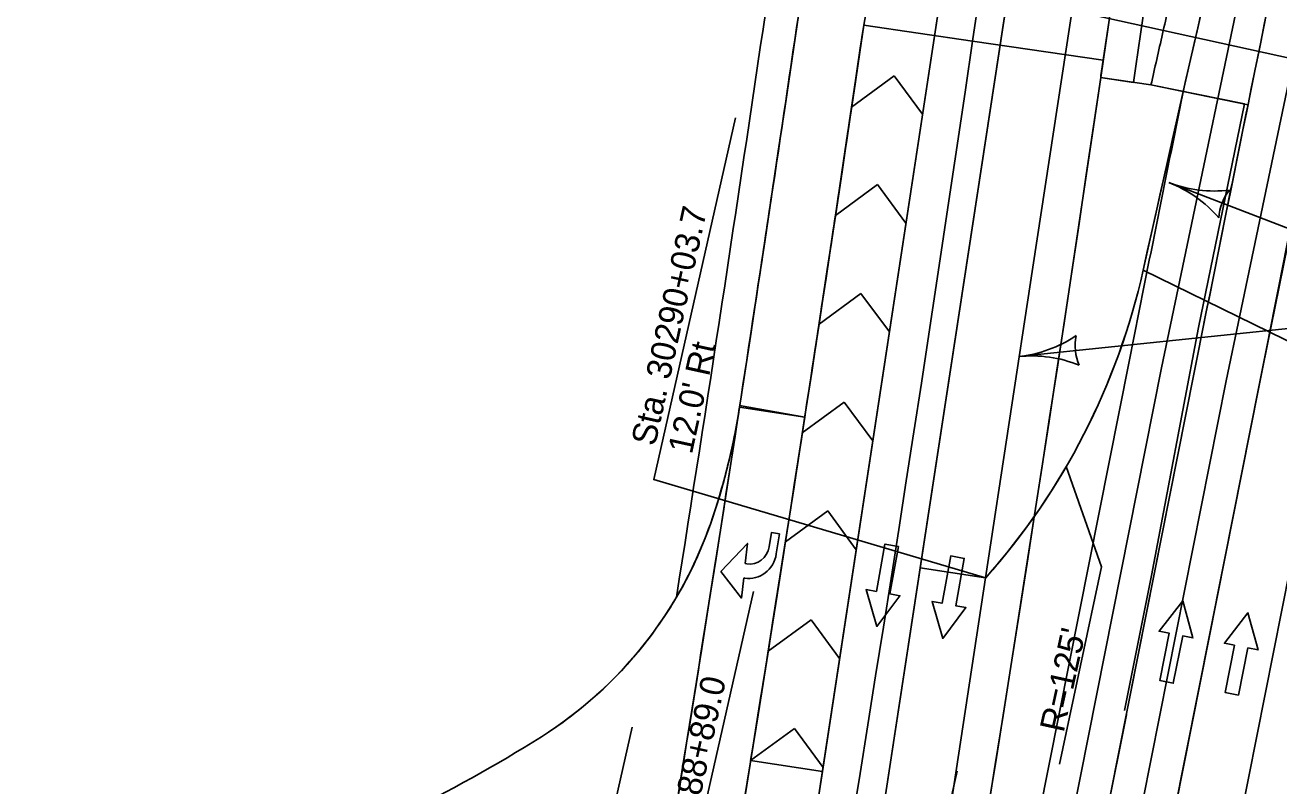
# Model space of a CAD drawing. Extents: x 14104283 to 14120882, y 8635219 to 8671666.
# Drawn here: x 14107792.5 to 14108020.4, y 8639938.3 to 8640076.6 of the extents above; entities that cross this region are included whole.
import ezdxf

# ---------------------------------------------------------------- set-up
doc = ezdxf.new("R2010")
doc.units = 0
for name, color, linetype in [('Cell', 7, 'Continuous'), ('dsnNonPlotable', 7, 'Continuous'), ('dsnPaintExistingBrokenLaneLineWhite', 7, 'Continuous'), ('dsnPaintExistingChannelizingLaneWhite', 7, 'Continuous'), ('dsnPaintExistingEdgeLineRightWhite', 7, 'Continuous'), ('dsnPaintPlaceBrokenLaneLineWhite', 7, 'Continuous'), ('dsnPaintPlaceBrokenLaneWhite', 7, 'Continuous'), ('dsnPaintPlaceEdgeLineLeftYellow', 7, 'Continuous'), ('dsnPaintPlaceEdgeLineRightWhite', 7, 'Continuous'), ('dsnPaintRemoveEdgeLineWhite', 7, 'Continuous'), ('dsnPaintRemoveEdgeLineYellow', 7, 'Continuous'), ('dsnShadingPaved', 7, 'Continuous'), ('dsnStdLabel', 7, 'Continuous'), ('dsnStgShadingPrevPav', 7, 'Continuous'), ('Text', 7, 'Continuous')]:
    doc.layers.add(name, color=color, linetype=linetype)

msp = doc.modelspace()

# ---------------------------------------------------------------- linework, layer by layer
at = {"layer": 'Cell'}
for p, q in [((14107923.72, 8639978.66), (14107923.41, 8639978.71)), ((14107923.13, 8639976.09), (14107923.31, 8639976.06))]:
    msp.add_line(p, q, dxfattribs=at)
for points in [[(14107929.06, 8639980.47), (14107929.64, 8639984.1), (14107928.16, 8639984.34), (14107927.75, 8639981.74)], [(14107929.06, 8639980.47), (14107929.64, 8639984.1), (14107928.16, 8639984.34), (14107927.75, 8639981.74)], [(14107923.41, 8639978.71), (14107923.81, 8639982.37), (14107918.97, 8639977.29)], [(14107923.41, 8639978.71), (14107923.81, 8639982.37), (14107918.97, 8639977.29)], [(14107947.24, 8639973.65), (14107945.39, 8639973.99), (14107947.35, 8639967.28), (14107951.54, 8639972.87), (14107949.7, 8639973.2), (14107951.26, 8639981.81), (14107948.8, 8639982.26), (14107947.24, 8639973.65)], [(14107959.2, 8639971.49), (14107957.36, 8639971.82), (14107959.31, 8639965.11), (14107963.51, 8639970.7), (14107961.66, 8639971.04), (14107963.23, 8639979.65), (14107960.77, 8639980.1), (14107959.2, 8639971.49)], [(14107918.97, 8639977.29), (14107922.73, 8639972.43), (14107923.13, 8639976.09)], [(14107918.97, 8639977.29), (14107922.73, 8639972.43), (14107923.13, 8639976.09)], [(14107923.72, 8639978.66), (14107923.41, 8639978.71)], [(14107923.13, 8639976.09), (14107923.31, 8639976.06)], [(14108002.93, 8639965.55), (14108004.77, 8639965.19), (14108002.93, 8639971.93), (14107998.64, 8639966.41), (14108000.48, 8639966.04), (14107998.76, 8639957.46), (14108001.21, 8639956.97), (14108002.93, 8639965.55)], [(14108014.78, 8639963.38), (14108016.62, 8639963.02), (14108014.78, 8639969.76), (14108010.49, 8639964.24), (14108012.33, 8639963.87), (14108010.61, 8639955.29), (14108013.06, 8639954.8), (14108014.78, 8639963.38)]]:
    msp.add_lwpolyline(points, dxfattribs=at)
for points in [[(14107948.8, 8639982.26), (14107951.26, 8639981.81), (14107949.7, 8639973.2), (14107951.54, 8639972.87), (14107947.35, 8639967.28), (14107945.39, 8639973.99), (14107947.24, 8639973.65)], [(14107960.77, 8639980.1), (14107963.23, 8639979.65), (14107961.66, 8639971.04), (14107963.51, 8639970.7), (14107959.31, 8639965.11), (14107957.36, 8639971.82), (14107959.2, 8639971.49)], [(14108001.21, 8639956.97), (14107998.76, 8639957.46), (14108000.48, 8639966.04), (14107998.64, 8639966.41), (14108002.93, 8639971.93), (14108004.77, 8639965.19), (14108002.93, 8639965.55)], [(14108013.06, 8639954.8), (14108010.61, 8639955.29), (14108012.33, 8639963.87), (14108010.49, 8639964.24), (14108014.78, 8639969.76), (14108016.62, 8639963.02), (14108014.78, 8639963.38)]]:
    msp.add_lwpolyline(points, close=True, dxfattribs=at)
for centre, major_axis in [((14107924.3, 8639982.29), (0.58, 3.63)), ((14107924.3, 8639982.29), (0.58, 3.63)), ((14107924.14, 8639981.25), (0.83, 5.19)), ((14107924.14, 8639981.25), (0.83, 5.19))]:
    msp.add_ellipse(centre, major_axis=major_axis, ratio=0.9474, start_param=3.141593, end_param=4.712389, dxfattribs=at)
at = {"layer": 'dsnNonPlotable'}
msp.add_lwpolyline([(14107218.44, 8638642.33), (14107554.83, 8640173.31), (14108541.3, 8639956.56), (14108204.91, 8638425.58)], close=True, dxfattribs=at)
at = {"layer": 'dsnPaintExistingBrokenLaneLineWhite'}
msp.add_line((14107897.23, 8639597.8), (14108002.8, 8640289.8), dxfattribs=at)
at = {"layer": 'dsnPaintExistingChannelizingLaneWhite'}
for p, q in [((14107990.94, 8640291.61), (14107937.44, 8639940.91)), ((14107950.5, 8640067.36), (14107942.75, 8640061.66)), ((14107955.65, 8640060.36), (14107950.5, 8640067.36)), ((14107947.47, 8640047.59), (14107939.81, 8640041.95)), ((14107952.63, 8640040.58), (14107947.47, 8640047.59)), ((14107944.45, 8640027.82), (14107936.82, 8640022.21)), ((14107949.61, 8640020.8), (14107944.45, 8640027.82)), ((14107941.42, 8640008.05), (14107933.79, 8640002.44)), ((14107946.6, 8640001.01), (14107941.42, 8640008.05)), ((14107938.4, 8639988.28), (14107930.71, 8639982.63)), ((14107943.58, 8639981.23), (14107938.4, 8639988.28)), ((14107935.37, 8639968.51), (14107927.58, 8639962.78)), ((14107940.57, 8639961.44), (14107935.37, 8639968.51)), ((14107932.34, 8639948.74), (14107924.4, 8639942.9)), ((14107937.55, 8639941.65), (14107932.34, 8639948.74)), ((14107937.44, 8639940.91), (14107924.4, 8639942.9))]:
    msp.add_line(p, q, dxfattribs=at)
for centre, radius, start, end in [((14098631.47, 8641759.51), 9464.31, 349.754833, 350.304675), ((14098576.76, 8641447.78), 9468, 350.854404, 351.672846)]:
    msp.add_arc(centre, radius, start, end, dxfattribs=at)
at = {"layer": 'dsnPaintExistingEdgeLineRightWhite'}
for centre, radius, start, end in [((14098576.76, 8641447.78), 9456, 351.234366, 351.672846), ((14107805.1, 8640025.1), 118.64, 340.7006, 351.1759), ((14107846.26, 8640010.61), 75, 302.3186, 340.7615), ((14107752.7, 8640158.5), 250, 288.9195, 302.3186)]:
    msp.add_arc(centre, radius, start, end, dxfattribs=at)
at = {"layer": 'dsnPaintPlaceBrokenLaneLineWhite'}
msp.add_lwpolyline([(14107985.48, 8639853.32), (14108001.11, 8639932.06), (14108016.73, 8640010.8), (14108028.7, 8640069.55), (14108040.67, 8640128.3), (14108053.24, 8640186.93), (14108065.81, 8640245.56), (14108082.44, 8640321.29), (14108099.08, 8640397.01)], dxfattribs=at)
at = {"layer": 'dsnPaintPlaceBrokenLaneWhite'}
msp.add_lwpolyline([(14107843.64, 8639178.31), (14107884.58, 8639364.68), (14107924.33, 8639550.14), (14107962.2, 8639735.99), (14107989.47, 8639873.39), (14108016.73, 8640010.79)], dxfattribs=at)
at = {"layer": 'dsnPaintPlaceEdgeLineLeftYellow'}
for p, q in [((14108014.66, 8640287.99), (14107975.68, 8640032.58)), ((14107975.68, 8640032.58), (14107967.07, 8639976.09))]:
    msp.add_line(p, q, dxfattribs=at)
for centre, radius, start, end in [((14119521.42, 8637460.89), 11808.99, 166.339341, 167.424478), ((14107873.73, 8640059.23), 125, 318.3035, 347.4245)]:
    msp.add_arc(centre, radius, start, end, dxfattribs=at)
at = {"layer": 'dsnPaintPlaceEdgeLineRightWhite'}
msp.add_lwpolyline([(14107997.25, 8639850.98), (14108001.23, 8639871.02), (14108028.5, 8640008.43), (14108052.42, 8640125.85), (14108077.53, 8640243.01), (14108094.16, 8640318.73), (14108110.8, 8640394.44)], dxfattribs=at)
at = {"layer": 'dsnPaintRemoveEdgeLineWhite'}
msp.add_lwpolyline([(14107811.17, 8639057.08), (14107844.94, 8639211.53), (14107878.72, 8639365.97), (14107918.46, 8639551.34), (14107956.3, 8639737.1), (14108010.84, 8640011.94), (14108059.95, 8640246.87), (14108093.19, 8640398.18)], dxfattribs=at)
at = {"layer": 'dsnPaintRemoveEdgeLineYellow'}
msp.add_lwpolyline([(14107799.44, 8639059.65), (14107867, 8639368.55), (14107944.53, 8639739.44), (14107999.07, 8640014.27), (14108048.23, 8640249.45), (14108081.5, 8640400.87)], dxfattribs=at)
at = {"layer": 'dsnShadingPaved'}
for p, q in [((14107885.37, 8639599.61), (14107990.94, 8640291.61)), ((14108002.8, 8640289.8), (14107897.23, 8639597.8)), ((14107955.22, 8639977.91), (14108002.8, 8640289.8)), ((14108014.66, 8640287.99), (14107975.68, 8640032.58)), ((14107995.73, 8640032.02), (14108003.03, 8640064.5)), ((14108003.03, 8640064.5), (14108014.79, 8640062.11)), ((14108014.79, 8640062.11), (14108003.03, 8640064.5)), ((14107975.68, 8640032.58), (14107967.07, 8639976.1)), ((14108004.96, 8640013.11), (14107973.63, 8639855.23)), ((14107922.35, 8640007.41), (14107934.24, 8640005.32)), ((14107922.38, 8640007.15), (14107934.24, 8640005.32)), ((14107897.23, 8639597.8), (14107955.22, 8639977.91)), ((14107967.07, 8639976.1), (14107955.22, 8639977.91)), ((14107955.22, 8639977.91), (14107967.07, 8639976.1)), ((14107949.24, 8639859.12), (14107967.08, 8639976.1)), ((14107967.08, 8639976.1), (14107949.24, 8639859.12)), ((14107937.44, 8639940.91), (14107908.71, 8639752.63)), ((14107924.4, 8639942.9), (14107937.44, 8639940.91))]:
    msp.add_line(p, q, dxfattribs=at)
for points in [[(14107831.92, 8639180.86), (14107872.85, 8639367.2), (14107912.58, 8639552.57), (14107950.43, 8639738.33), (14108004.96, 8640013.11)], [(14108028.5, 8640008.43), (14107973.96, 8639733.6), (14107936.08, 8639547.66), (14107896.3, 8639362.11), (14107855.36, 8639175.71)]]:
    msp.add_lwpolyline(points, dxfattribs=at)
for centre, radius, start, end in [((14119521.42, 8637460.89), 11808.99, 166.339341, 167.262962), ((14119581.23, 8637715.91), 11802, 167.610212, 168.776036), ((14119581.23, 8637715.91), 11802, 167.610212, 168.533379), ((14098631.47, 8641759.51), 9464.31, 349.754833, 350.304675), ((14098576.76, 8641447.78), 9456, 351.23682, 351.672846), ((14098576.76, 8641447.78), 9468, 351.23682, 351.672846), ((14119581.23, 8637715.91), 11802, 168.533379, 168.776036), ((14107873.73, 8640059.23), 125, 318.3138, 347.4245), ((14107803.78, 8640025.43), 120, 340.7615, 351.2368), ((14098576.76, 8641447.78), 9468, 350.854404, 351.23682), ((14107846.26, 8640010.61), 75, 302.3186, 340.7615), ((14107752.7, 8640158.5), 250, 288.9195, 302.3186)]:
    msp.add_arc(centre, radius, start, end, dxfattribs=at)
at = {"layer": 'dsnStdLabel'}
for q in [(14108000.38, 8640047.95), (14107973.08, 8640016.33)]:
    msp.add_line((14108059.33, 8640025.28), q, dxfattribs=at)
for centre, radius, start, end in [((14107992.15, 8640026.53), 22.95, 40.892, 68.9633), ((14108008.62, 8640069.37), 22.95, 248.9631, 277.0344), ((14108018.34, 8640041.04), 8.86, 141.2289, 176.6974), ((14107970.71, 8640039.16), 22.95, 275.922, 303.9932), ((14107992.22, 8640018.31), 8.86, 168.1878, 203.6562), ((14107975.45, 8639993.5), 22.95, 67.8508, 95.9221)]:
    msp.add_arc(centre, radius, start, end, dxfattribs=at)
at = {"layer": 'dsnStgShadingPrevPav'}
for p, q in [((14107944.94, 8640076.58), (14107964.73, 8640073.68)), ((14107964.73, 8640073.68), (14107944.94, 8640076.58)), ((14107964.73, 8640073.68), (14107988.48, 8640070.2)), ((14107988.48, 8640070.2), (14107964.73, 8640073.68)), ((14107993.95, 8640066.16), (14107988.01, 8640067.03)), ((14108014.17, 8640062.24), (14107997.15, 8640065.69)), ((14108014.79, 8640062.11), (14108003.03, 8640064.5)), ((14107993.19, 8640015.44), (14107938.65, 8639740.6)), ((14107993.19, 8640015.44), (14107938.65, 8639740.6)), ((14107950.42, 8639738.27), (14108004.96, 8640013.11)), ((14108016.73, 8640010.77), (14107962.19, 8639735.93)), ((14108016.73, 8640010.77), (14107962.19, 8639735.93)), ((14107950.42, 8639738.27), (14107992.68, 8639951.24))]:
    msp.add_line(p, q, dxfattribs=at)
for points in [[(14107988.01, 8640067.03), (14107997.15, 8640065.69), (14108003.03, 8640064.5)], [(14107992.32, 8639951.99), (14107997.25, 8639976.55), (14108005.78, 8640021.62), (14108014.17, 8640062.24)]]:
    msp.add_lwpolyline(points, dxfattribs=at)
for centre, radius, start, end in [((14119581.23, 8637715.91), 11790, 167.610212, 168.776036), ((14119581.23, 8637715.91), 11790, 167.610212, 168.776036), ((14098576.76, 8641447.78), 9488, 351.672846, 352.222077), ((14098576.76, 8641447.78), 9488, 351.672846, 352.222078), ((14098576.76, 8641447.78), 9512, 351.653537, 352.222077), ((14098576.76, 8641447.78), 9512, 351.672846, 352.222077), ((14098576.76, 8641447.78), 9518, 351.653537, 352.222077), ((14098576.76, 8641447.78), 9456, 348.449343, 351.672846), ((14098576.76, 8641447.78), 9450, 351.019031, 351.672846), ((14098576.76, 8641447.78), 9456, 351.23682, 351.672846), ((14098576.76, 8641447.78), 9468, 347.807255, 351.672846), ((14098576.76, 8641447.78), 9468, 348.194582, 351.672846), ((14098576.76, 8641447.78), 9488, 348.202524, 351.672846), ((14098576.76, 8641447.78), 9488, 348.202524, 351.672846), ((14098576.76, 8641447.78), 9512, 351.653537, 351.672846), ((14098576.76, 8641447.78), 9512, 348.176197, 351.653537), ((14098576.76, 8641447.78), 9512, 348.212012, 351.653537), ((14119581.23, 8637715.91), 11814, 168.533379, 168.776036), ((14119581.23, 8637715.91), 11814, 168.533379, 168.776036), ((14119581.23, 8637715.91), 11802, 168.533379, 168.776036), ((14098576.76, 8641447.78), 9456, 350.195701, 351.23682), ((14107803.78, 8640025.43), 120, 340.7615, 351.2368), ((14107803.78, 8640025.43), 120, 340.7615, 351.2368), ((14107846.26, 8640010.61), 75, 329.5302, 340.7615), ((14107846.26, 8640010.61), 75, 329.5302, 340.7615), ((14107846.26, 8640010.61), 75, 302.3186, 329.5302), ((14107752.7, 8640158.5), 250, 288.9195, 302.3186)]:
    msp.add_arc(centre, radius, start, end, dxfattribs=at)
msp.add_open_spline([(14107997.15, 8640065.69), (14107997.85, 8640068.79), (14107999.25, 8640074.98), (14108001.36, 8640084.27), (14108003.48, 8640093.55), (14108005.61, 8640102.84), (14108007.74, 8640112.12), (14108009.88, 8640121.4), (14108012.03, 8640130.68), (14108014.18, 8640139.95), (14108016.35, 8640149.23), (14108018.52, 8640158.5), (14108020.7, 8640167.77), (14108022.88, 8640177.04), (14108025.07, 8640186.31), (14108027.27, 8640195.57), (14108029.48, 8640204.83), (14108031.7, 8640214.1), (14108033.92, 8640223.35), (14108036.15, 8640232.61), (14108038.39, 8640241.87), (14108039.88, 8640248.03), (14108040.63, 8640251.12)], degree=3, dxfattribs=at)
at = {"layer": 'Text'}
for points in [[(14107921.64, 8640059.71), (14107906.78, 8639993.97), (14107967.08, 8639976.1)], [(14108042.52, 8639940.64), (14108055.75, 8640002.65), (14107995.73, 8640032.02)], [(14107980.53, 8639942.24), (14107988.18, 8639978.12), (14107981.75, 8639996.33)], [(14107924.93, 8639973.66), (14107910.94, 8639911.81), (14107955.17, 8639858.22)], [(14107902.87, 8639949), (14107888, 8639883.25), (14107949.23, 8639859.12)], [(14107961.95, 8639940.98), (14107947.97, 8639879.13), (14107967.03, 8639856.41)]]:
    msp.add_lwpolyline(points, dxfattribs=at)

# ---------------------------------------------------------------- texts
for s, height, p in [('Sta. 30290+03.7', 4.4845, (14107907.03, 8639999.9)), ("12.0' Rt", 4.484, (14107913.71, 8639998.43)), ("R=125'", 4.484, (14107981.27, 8639947.85)), ('Sta. 1288+89.0', 4.4845, (14107911.2, 8639917.75))]:
    msp.add_text(s, height=height, rotation=77.6078, dxfattribs=at).set_placement(p)

doc.saveas('drawing.dxf')
